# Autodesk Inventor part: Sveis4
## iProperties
Created: 2009-09
Part Number: Sveis4
Document SubType Name: Modeling
Designer: TB
Mass: 12.2964 g
Surface Area: 59.6118 cm^2
Volume: 12.2964 cm^3
Density: 1 g/cm^3
Author: TB
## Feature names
1. Extrusion1
